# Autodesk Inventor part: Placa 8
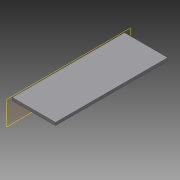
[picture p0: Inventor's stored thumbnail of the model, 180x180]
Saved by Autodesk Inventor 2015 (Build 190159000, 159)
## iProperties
Created: 2015-04
Part Number: Placa 8
Material: Generic
Document SubType Name: Modeling
Designer: suporte
Density: 1 g/cm^3
Appearance: Default
Author: suporte
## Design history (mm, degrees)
workplane "Work Plane1"
sketch "Sketch1"
  geometry: L1 (-36.9, -512.349)-(-36.9, 6.25) reference; L2 (-50, -512.349)-(-50, 6.25) reference; L3 (-36.9, -512.349)-(-50, -512.349); L4 (-50, -512.349)-(-50, 6.25); L5 (-50, 6.25)-(-36.9, 6.25); L6 (-36.9, 6.25)-(-36.9, -512.349); 1 further point
  constraints: 8 end point, 2 parallel, 1 horizontal, 1 perpendicular
extrude "Extrusion1" new body sketch "Sketch1" distance "d0" = 187.5; taper "d1" = 0 deg
body "Solid1"
node "Reference1"
node "Reference2"
